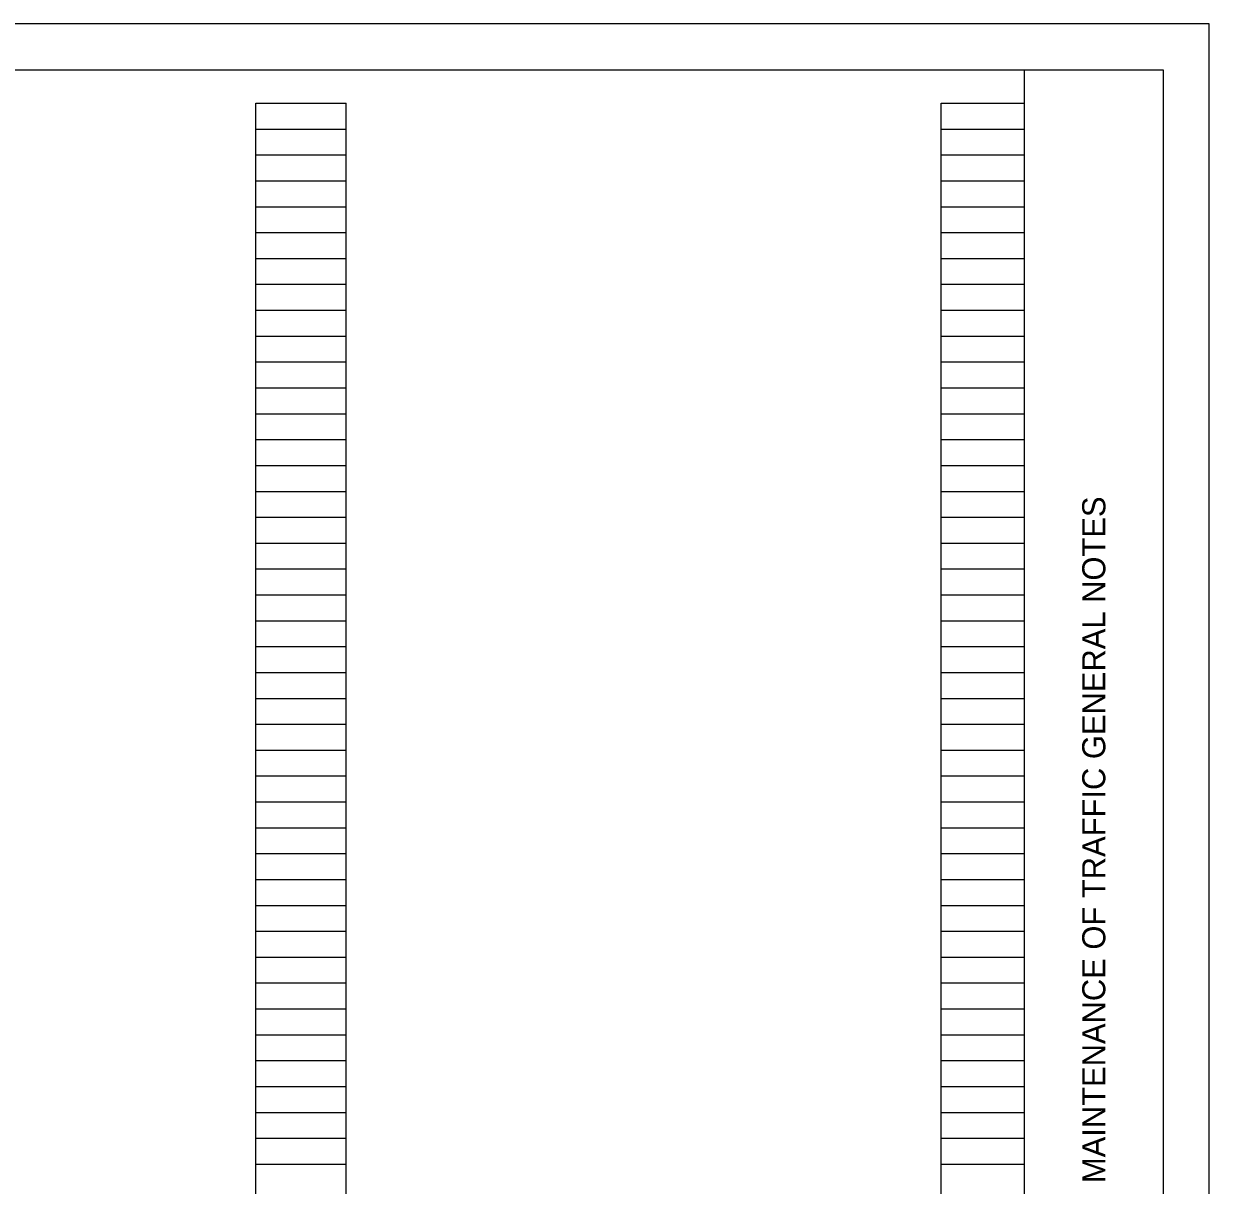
# Model space of a CAD drawing. Extents: x -16.1 to 34, y 0 to 22.
# Drawn here: x 21.17 to 34, y 9.43 to 22 of the extents above; entities that cross this region are included whole.
import ezdxf

# ---------------------------------------------------------------- set-up
doc = ezdxf.new("R2010")
doc.units = 0
for name, color, linetype in [('SH_Border', 7, 'Continuous'), ('SH_Cut_Line', 7, 'Continuous'), ('SH_Data', 7, 'Continuous')]:
    doc.layers.add(name, color=color, linetype=linetype)

msp = doc.modelspace()

# ---------------------------------------------------------------- linework, layer by layer
at = {"layer": 'SH_Border'}
msp.add_line((32, 0.5), (32, 21.5), dxfattribs=at)
msp.add_lwpolyline([(1.5, 21.5), (33.5, 21.5), (33.5, 0.5), (1.5, 0.5)], close=True, dxfattribs=at)
at = {"layer": 'SH_Cut_Line'}
msp.add_lwpolyline([(0, 0), (34, 0), (34, 22), (0, 22)], close=True, dxfattribs=at)
at = {"layer": 'SH_Data'}
for p, q in [((23.68, 0.98), (23.68, 21.14)), ((23.68, 21.14), (24.66, 21.14)), ((24.66, 0.98), (24.66, 21.14)), ((31.1, 0.98), (31.1, 21.14)), ((31.1, 21.14), (32, 21.14)), ((32, 0.98), (32, 21.14)), ((23.68, 20.86), (24.66, 20.86)), ((31.1, 20.86), (32, 20.86)), ((23.68, 20.58), (24.66, 20.58)), ((31.1, 20.58), (32, 20.58)), ((23.68, 20.3), (24.66, 20.3)), ((31.1, 20.3), (32, 20.3)), ((23.68, 20.02), (24.66, 20.02)), ((31.1, 20.02), (32, 20.02)), ((23.68, 19.74), (24.66, 19.74)), ((31.1, 19.74), (32, 19.74)), ((23.68, 19.46), (24.66, 19.46)), ((31.1, 19.46), (32, 19.46)), ((23.68, 19.18), (24.66, 19.18)), ((31.1, 19.18), (32, 19.18)), ((23.68, 18.9), (24.66, 18.9)), ((31.1, 18.9), (32, 18.9)), ((23.68, 18.62), (24.66, 18.62)), ((31.1, 18.62), (32, 18.62)), ((23.68, 18.34), (24.66, 18.34)), ((31.1, 18.34), (32, 18.34)), ((23.68, 18.06), (24.66, 18.06)), ((31.1, 18.06), (32, 18.06)), ((23.68, 17.78), (24.66, 17.78)), ((31.1, 17.78), (32, 17.78)), ((23.68, 17.5), (24.66, 17.5)), ((31.1, 17.5), (32, 17.5)), ((23.68, 17.22), (24.66, 17.22)), ((31.1, 17.22), (32, 17.22)), ((23.68, 16.94), (24.66, 16.94)), ((31.1, 16.94), (32, 16.94)), ((23.68, 16.66), (24.66, 16.66)), ((31.1, 16.66), (32, 16.66)), ((23.68, 16.38), (24.66, 16.38)), ((31.1, 16.38), (32, 16.38)), ((23.68, 16.1), (24.66, 16.1)), ((31.1, 16.1), (32, 16.1)), ((23.68, 15.82), (24.66, 15.82)), ((31.1, 15.82), (32, 15.82)), ((23.68, 15.54), (24.66, 15.54)), ((31.1, 15.54), (32, 15.54)), ((23.68, 15.26), (24.66, 15.26)), ((31.1, 15.26), (32, 15.26)), ((23.68, 14.98), (24.66, 14.98)), ((31.1, 14.98), (32, 14.98)), ((23.68, 14.7), (24.66, 14.7)), ((31.1, 14.7), (32, 14.7)), ((23.68, 14.42), (24.66, 14.42)), ((31.1, 14.42), (32, 14.42)), ((23.68, 14.14), (24.66, 14.14)), ((31.1, 14.14), (32, 14.14)), ((23.68, 13.86), (24.66, 13.86)), ((31.1, 13.86), (32, 13.86)), ((23.68, 13.58), (24.66, 13.58)), ((31.1, 13.58), (32, 13.58)), ((23.68, 13.3), (24.66, 13.3)), ((31.1, 13.3), (32, 13.3)), ((23.68, 13.02), (24.66, 13.02)), ((31.1, 13.02), (32, 13.02)), ((23.68, 12.74), (24.66, 12.74)), ((31.1, 12.74), (32, 12.74)), ((23.68, 12.46), (24.66, 12.46)), ((31.1, 12.46), (32, 12.46)), ((23.68, 12.18), (24.66, 12.18)), ((31.1, 12.18), (32, 12.18)), ((23.68, 11.9), (24.66, 11.9)), ((31.1, 11.9), (32, 11.9)), ((23.68, 11.62), (24.66, 11.62)), ((31.1, 11.62), (32, 11.62)), ((23.68, 11.34), (24.66, 11.34)), ((31.1, 11.34), (32, 11.34)), ((23.68, 11.06), (24.66, 11.06)), ((31.1, 11.06), (32, 11.06)), ((23.68, 10.78), (24.66, 10.78)), ((31.1, 10.78), (32, 10.78)), ((23.68, 10.5), (24.66, 10.5)), ((31.1, 10.5), (32, 10.5)), ((23.68, 10.22), (24.66, 10.22)), ((31.1, 10.22), (32, 10.22)), ((23.68, 9.94), (24.66, 9.94)), ((31.1, 9.94), (32, 9.94)), ((23.68, 9.66), (24.66, 9.66)), ((31.1, 9.66), (32, 9.66))]:
    msp.add_line(p, q, dxfattribs=at)

# ---------------------------------------------------------------- texts
msp.add_text('MAINTENANCE OF TRAFFIC GENERAL NOTES', height=0.25, rotation=90, dxfattribs=at).set_placement((32.875, 9.455))

doc.saveas('drawing.dxf')
